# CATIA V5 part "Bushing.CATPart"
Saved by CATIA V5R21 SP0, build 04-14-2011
Part number: Bushing
Bounding box of the stored display mesh (mm): x -13.45 to 13.45, y 0 to 63, z -13.45 to 13.45
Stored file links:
  D:\CATIA V5R21 E-RESOURCES\CATIA-V5R21\catia-v5r21-Prts\c12_catia_v5r21_prt\c12_catia_v5r21figr_12-53\Bushing.CATPart
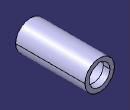
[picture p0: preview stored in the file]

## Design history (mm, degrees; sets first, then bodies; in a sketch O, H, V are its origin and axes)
Body1 (main body)
  Sketch1 on zx-plane, origin (0, 0, 0), H (-1, 0, 0), V (0, 0, 1)
    circle A1 centre (0, 0) radius 9.5
    circle A2 centre (0, 0) radius 13.45
    radius A1 = 9.5
    radius A2 = 13.45
  Pad1: profile Sketch1, direction (0, 1, 0), length 63
  Sketch2 on face of Pad1, origin (0, 63, 0), H (-1, 0, 0), V (0, 0, 1)
    line L1 (-1.5, 9.3808) -> (1.5, 9.3808)
    line L2 (1.5, 9.3808) -> (1.5, 10.1808)
    line L3 (1.5, 10.1808) -> (-1.5, 10.1808)
    line L4 (-1.5, 10.1808) -> (-1.5, 9.3808)
    point P2 (1.5, 9.3808)
    reference projected circle E1 centre (0, 0) radius 9.5 from edge of Pad1
    length L3 = 3
    length L2 = 0.8
    distance V L4 = 1.5
    horizontal: L1 H, L3 H
    vertical: L2 V, L4 V
    coincidence: P2 E1
  Pocket1: profile Sketch2, direction (0, -1, 0), through (limit type 6)
  Sketch3 on xy-plane, origin (0, 0, 0), H (1, 0, 0), V (0, 1, 0)
    line L1 (9.5, 57) -> (10.3, 57)
    line L2 (10.3, 57) -> (10.3, 49)
    line L3 (10.3, 49) -> (9.5, 49)
    line L4 (9.5, 49) -> (9.5, 57)
    reference projected line E1 (13.45, 63) -> (-13.45, 63) from edge of Pad1
    length L2 = 8
    length L1 = 0.8
    distance L3 E1 = 14
    distance V L4 = 9.5
    horizontal: L1 H, L3 H
    vertical: L2 V, L4 V
  Groove1: profile Sketch3, axis axis of face of Pad1, angle 360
